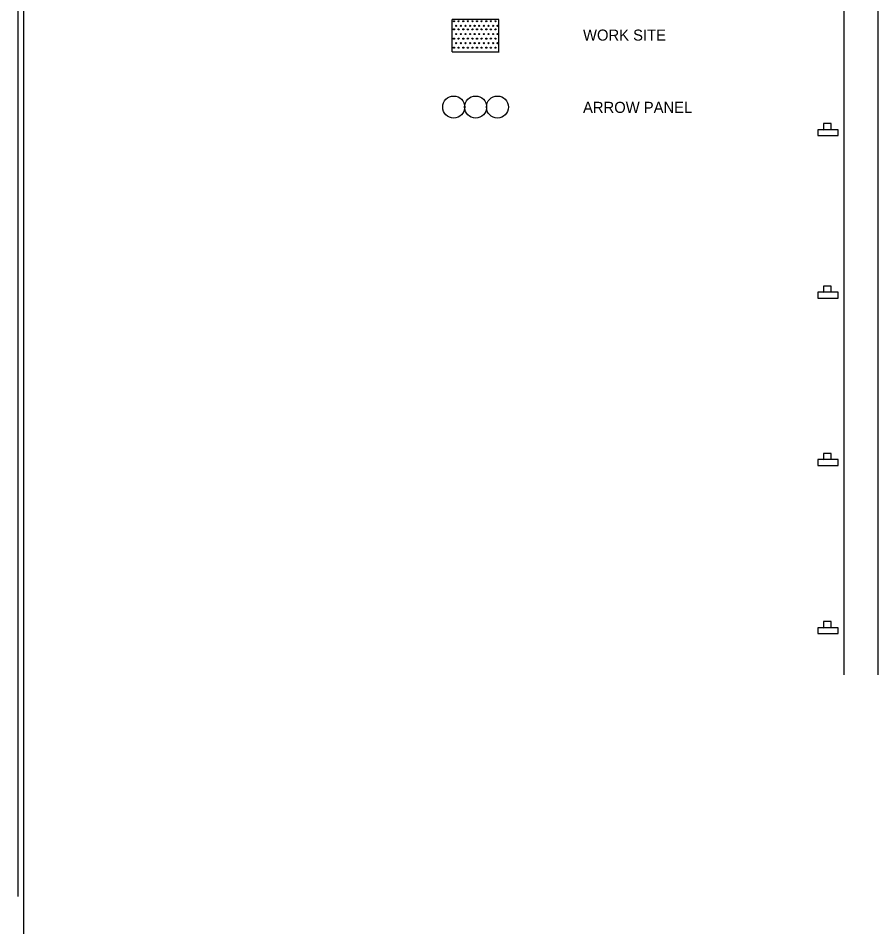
# Model space of a CAD drawing. Extents: x 15310.1 to 15319.5, y 15309 to 15319.1.
# Drawn here: x 15310.134 to 15314.797, y 15309.385 to 15314.35 of the extents above; entities that cross this region are included whole.
import ezdxf

# ---------------------------------------------------------------- set-up
doc = ezdxf.new("R2010")
doc.units = 0
for name, color, linetype in [('DETL-LINE', 7, 'Continuous'), ('DETL-NOTE', 7, 'Continuous'), ('USER-BORD', 7, 'Continuous')]:
    doc.layers.add(name, color=color, linetype=linetype)

# ---------------------------------------------------------------- blocks, each defined once
blk = doc.blocks.new('PANEL0')
at = {"layer": 'USER-BORD'}
for centre in [(0.0309, -0.0012), (0.0928, -0.0012), (0.1546, -0.0012)]:
    blk.add_circle(centre, 0.0312, dxfattribs=at)
blk = doc.blocks.new('SIGN15')
at = {"layer": 'USER-BORD'}
for points in [[(-0.013, 0.018), (0.011, 0.019), (0.011, 0.037), (-0.013, 0.037)], [(-0.031, 0.018), (-0.031, 0), (0.032, 0), (0.032, 0.018)]]:
    blk.add_lwpolyline(points, close=True, dxfattribs=at)

msp = doc.modelspace()

# ---------------------------------------------------------------- linework, layer by layer
at = {"layer": 'DETL-LINE'}
for p, q in [((15314.614, 15318.4337), (15314.614, 15310.79)), ((15314.797, 15318.4337), (15314.797, 15310.79)), ((15310.1336, 15309.5875), (15310.1336, 15317.2313)), ((15310.1637, 15309.3853), (15310.1637, 15317.0291)), ((15312.742, 15314.343), (15312.488, 15314.343)), ((15312.742, 15314.343), (15312.488, 15314.343)), ((15312.742, 15314.343), (15312.488, 15314.343)), ((15312.742, 15314.343), (15312.488, 15314.343)), ((15312.4886, 15314.1689), (15312.4886, 15314.3429)), ((15312.4886, 15314.1689), (15312.4886, 15314.3429)), ((15312.497, 15314.334), (15312.497, 15314.334)), ((15312.498, 15314.334), (15312.498, 15314.334)), ((15312.51, 15314.309), (15312.51, 15314.309)), ((15312.51, 15314.309), (15312.51, 15314.309)), ((15312.523, 15314.334), (15312.523, 15314.334)), ((15312.523, 15314.334), (15312.523, 15314.334)), ((15312.535, 15314.309), (15312.535, 15314.309)), ((15312.535, 15314.309), (15312.535, 15314.309)), ((15312.547, 15314.334), (15312.547, 15314.334)), ((15312.548, 15314.334), (15312.548, 15314.334)), ((15312.56, 15314.309), (15312.56, 15314.309)), ((15312.56, 15314.309), (15312.56, 15314.309)), ((15312.572, 15314.334), (15312.572, 15314.334)), ((15312.573, 15314.334), (15312.573, 15314.334)), ((15312.585, 15314.309), (15312.585, 15314.309)), ((15312.585, 15314.309), (15312.585, 15314.309)), ((15312.597, 15314.334), (15312.597, 15314.334)), ((15312.598, 15314.334), (15312.598, 15314.334)), ((15312.61, 15314.309), (15312.61, 15314.309)), ((15312.61, 15314.309), (15312.61, 15314.309)), ((15312.623, 15314.334), (15312.623, 15314.334)), ((15312.623, 15314.334), (15312.623, 15314.334)), ((15312.635, 15314.309), (15312.635, 15314.309)), ((15312.635, 15314.309), (15312.635, 15314.309)), ((15312.647, 15314.334), (15312.647, 15314.334)), ((15312.647, 15314.334), (15312.647, 15314.334)), ((15312.659, 15314.309), (15312.659, 15314.309)), ((15312.659, 15314.309), (15312.659, 15314.309)), ((15312.672, 15314.334), (15312.672, 15314.334)), ((15312.673, 15314.334), (15312.673, 15314.334)), ((15312.685, 15314.309), (15312.685, 15314.309)), ((15312.685, 15314.309), (15312.685, 15314.309)), ((15312.697, 15314.334), (15312.697, 15314.334)), ((15312.698, 15314.334), (15312.698, 15314.334)), ((15312.71, 15314.309), (15312.71, 15314.309)), ((15312.71, 15314.309), (15312.71, 15314.309)), ((15312.723, 15314.334), (15312.723, 15314.334)), ((15312.723, 15314.334), (15312.723, 15314.334)), ((15312.735, 15314.309), (15312.735, 15314.309)), ((15312.735, 15314.309), (15312.735, 15314.309)), ((15312.742, 15314.169), (15312.742, 15314.343)), ((15312.742, 15314.169), (15312.742, 15314.343)), ((15312.742, 15314.169), (15312.742, 15314.343)), ((15312.742, 15314.169), (15312.742, 15314.343)), ((15312.497, 15314.29), (15312.497, 15314.29)), ((15312.498, 15314.29), (15312.498, 15314.29)), ((15312.51, 15314.265), (15312.51, 15314.265)), ((15312.523, 15314.29), (15312.523, 15314.29)), ((15312.523, 15314.29), (15312.523, 15314.29)), ((15312.535, 15314.265), (15312.535, 15314.265)), ((15312.547, 15314.29), (15312.547, 15314.29)), ((15312.548, 15314.29), (15312.548, 15314.29)), ((15312.56, 15314.265), (15312.56, 15314.265)), ((15312.572, 15314.29), (15312.572, 15314.29)), ((15312.573, 15314.29), (15312.573, 15314.29)), ((15312.585, 15314.265), (15312.585, 15314.265)), ((15312.597, 15314.29), (15312.597, 15314.29)), ((15312.598, 15314.29), (15312.598, 15314.29)), ((15312.61, 15314.265), (15312.61, 15314.265)), ((15312.623, 15314.29), (15312.623, 15314.29)), ((15312.623, 15314.29), (15312.623, 15314.29)), ((15312.635, 15314.265), (15312.635, 15314.265)), ((15312.647, 15314.29), (15312.647, 15314.29)), ((15312.647, 15314.29), (15312.647, 15314.29)), ((15312.659, 15314.265), (15312.659, 15314.265)), ((15312.672, 15314.29), (15312.672, 15314.29)), ((15312.673, 15314.29), (15312.673, 15314.29)), ((15312.685, 15314.265), (15312.685, 15314.265)), ((15312.697, 15314.29), (15312.697, 15314.29)), ((15312.698, 15314.29), (15312.698, 15314.29)), ((15312.71, 15314.265), (15312.71, 15314.265)), ((15312.723, 15314.29), (15312.723, 15314.29)), ((15312.723, 15314.29), (15312.723, 15314.29)), ((15312.735, 15314.265), (15312.735, 15314.265)), ((15312.497, 15314.24), (15312.497, 15314.24)), ((15312.498, 15314.24), (15312.498, 15314.24)), ((15312.51, 15314.215), (15312.51, 15314.215)), ((15312.51, 15314.215), (15312.51, 15314.215)), ((15312.523, 15314.24), (15312.523, 15314.24)), ((15312.523, 15314.24), (15312.523, 15314.24)), ((15312.535, 15314.215), (15312.535, 15314.215)), ((15312.535, 15314.215), (15312.535, 15314.215)), ((15312.547, 15314.24), (15312.547, 15314.24)), ((15312.548, 15314.24), (15312.548, 15314.24)), ((15312.56, 15314.215), (15312.56, 15314.215)), ((15312.56, 15314.215), (15312.56, 15314.215)), ((15312.572, 15314.24), (15312.572, 15314.24)), ((15312.573, 15314.24), (15312.573, 15314.24)), ((15312.585, 15314.215), (15312.585, 15314.215)), ((15312.585, 15314.215), (15312.585, 15314.215)), ((15312.597, 15314.24), (15312.597, 15314.24)), ((15312.598, 15314.24), (15312.598, 15314.24)), ((15312.61, 15314.215), (15312.61, 15314.215)), ((15312.61, 15314.215), (15312.61, 15314.215)), ((15312.623, 15314.24), (15312.623, 15314.24)), ((15312.623, 15314.24), (15312.623, 15314.24)), ((15312.635, 15314.215), (15312.635, 15314.215)), ((15312.635, 15314.215), (15312.635, 15314.215)), ((15312.647, 15314.24), (15312.647, 15314.24)), ((15312.647, 15314.24), (15312.647, 15314.24)), ((15312.659, 15314.215), (15312.659, 15314.215)), ((15312.659, 15314.215), (15312.659, 15314.215)), ((15312.672, 15314.24), (15312.672, 15314.24)), ((15312.673, 15314.24), (15312.673, 15314.24)), ((15312.685, 15314.215), (15312.685, 15314.215)), ((15312.685, 15314.215), (15312.685, 15314.215)), ((15312.697, 15314.24), (15312.697, 15314.24)), ((15312.698, 15314.24), (15312.698, 15314.24)), ((15312.71, 15314.215), (15312.71, 15314.215)), ((15312.71, 15314.215), (15312.71, 15314.215)), ((15312.723, 15314.24), (15312.723, 15314.24)), ((15312.723, 15314.24), (15312.723, 15314.24)), ((15312.735, 15314.215), (15312.735, 15314.215)), ((15312.735, 15314.215), (15312.735, 15314.215)), ((15312.4886, 15314.1689), (15312.7426, 15314.1689)), ((15312.497, 15314.191), (15312.497, 15314.191)), ((15312.498, 15314.191), (15312.498, 15314.191)), ((15312.523, 15314.191), (15312.523, 15314.191)), ((15312.523, 15314.191), (15312.523, 15314.191)), ((15312.547, 15314.191), (15312.547, 15314.191)), ((15312.548, 15314.191), (15312.548, 15314.191)), ((15312.572, 15314.191), (15312.572, 15314.191)), ((15312.573, 15314.191), (15312.573, 15314.191)), ((15312.597, 15314.191), (15312.597, 15314.191)), ((15312.598, 15314.191), (15312.598, 15314.191)), ((15312.623, 15314.191), (15312.623, 15314.191)), ((15312.623, 15314.191), (15312.623, 15314.191)), ((15312.647, 15314.191), (15312.647, 15314.191)), ((15312.647, 15314.191), (15312.647, 15314.191)), ((15312.672, 15314.191), (15312.672, 15314.191)), ((15312.673, 15314.191), (15312.673, 15314.191)), ((15312.697, 15314.191), (15312.697, 15314.191)), ((15312.698, 15314.191), (15312.698, 15314.191)), ((15312.723, 15314.191), (15312.723, 15314.191)), ((15312.723, 15314.191), (15312.723, 15314.191))]:
    msp.add_line(p, q, dxfattribs=at)
for centre in [(15312.4979, 15314.3339), (15312.5099, 15314.3091), (15312.5227, 15314.3339), (15312.5347, 15314.3091), (15312.5483, 15314.3339), (15312.5603, 15314.3091), (15312.5731, 15314.3339), (15312.5851, 15314.3091), (15312.5979, 15314.3339), (15312.6099, 15314.3091), (15312.6227, 15314.3339), (15312.6347, 15314.3091), (15312.6475, 15314.3339), (15312.6595, 15314.3091), (15312.6731, 15314.3339), (15312.6851, 15314.3091), (15312.6979, 15314.3339), (15312.7099, 15314.3091), (15312.7227, 15314.3339), (15312.7347, 15314.3091), (15312.4979, 15314.2902), (15312.5099, 15314.2646), (15312.5227, 15314.2902), (15312.5347, 15314.2646), (15312.5483, 15314.2902), (15312.5603, 15314.2646), (15312.5731, 15314.2902), (15312.5851, 15314.2646), (15312.5979, 15314.2902), (15312.6099, 15314.2646), (15312.6227, 15314.2902), (15312.6347, 15314.2646), (15312.6475, 15314.2902), (15312.6595, 15314.2646), (15312.6731, 15314.2902), (15312.6851, 15314.2646), (15312.6979, 15314.2902), (15312.7099, 15314.2646), (15312.7227, 15314.2902), (15312.7347, 15314.2646), (15312.4979, 15314.2398), (15312.5099, 15314.215), (15312.5227, 15314.2398), (15312.5347, 15314.215), (15312.5483, 15314.2398), (15312.5603, 15314.215), (15312.5731, 15314.2398), (15312.5851, 15314.215), (15312.5979, 15314.2398), (15312.6099, 15314.215), (15312.6227, 15314.2398), (15312.6347, 15314.215), (15312.6475, 15314.2398), (15312.6595, 15314.215), (15312.6731, 15314.2398), (15312.6851, 15314.215), (15312.6979, 15314.2398), (15312.7099, 15314.215), (15312.7227, 15314.2398), (15312.7347, 15314.215), (15312.4979, 15314.1906), (15312.5227, 15314.1906), (15312.5483, 15314.1906), (15312.5731, 15314.1906), (15312.5979, 15314.1906), (15312.6227, 15314.1906), (15312.6475, 15314.1906), (15312.6731, 15314.1906), (15312.6979, 15314.1906), (15312.7227, 15314.1906)]:
    msp.add_circle(centre, 0.00291, dxfattribs=at)

# ---------------------------------------------------------------- block references
for name, p, xscale, yscale in [('PANEL0', (15312.437, 15313.871), 1.9200000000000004, 1.9200000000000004), ('SIGN15', (15314.526, 15313.714), 1.7523809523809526, 1.7523809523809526), ('SIGN15', (15314.526, 15312.833), 1.7523809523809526, 1.7523809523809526), ('SIGN15', (15314.526, 15311.925), 1.7523809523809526, 1.7523809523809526), ('SIGN15', (15314.526, 15311.013), 1.7523809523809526, 1.7523809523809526)]:
    msp.add_blockref(name, p, dxfattribs=dict(at, xscale=xscale, yscale=yscale))

# ---------------------------------------------------------------- texts
at = {"layer": 'DETL-NOTE'}
for s, p in [('WORK SITE', (15313.198, 15314.229)), ('ARROW PANEL', (15313.198, 15313.837))]:
    msp.add_text(s, height=0.06, dxfattribs=at).set_placement(p)

doc.saveas('drawing.dxf')
